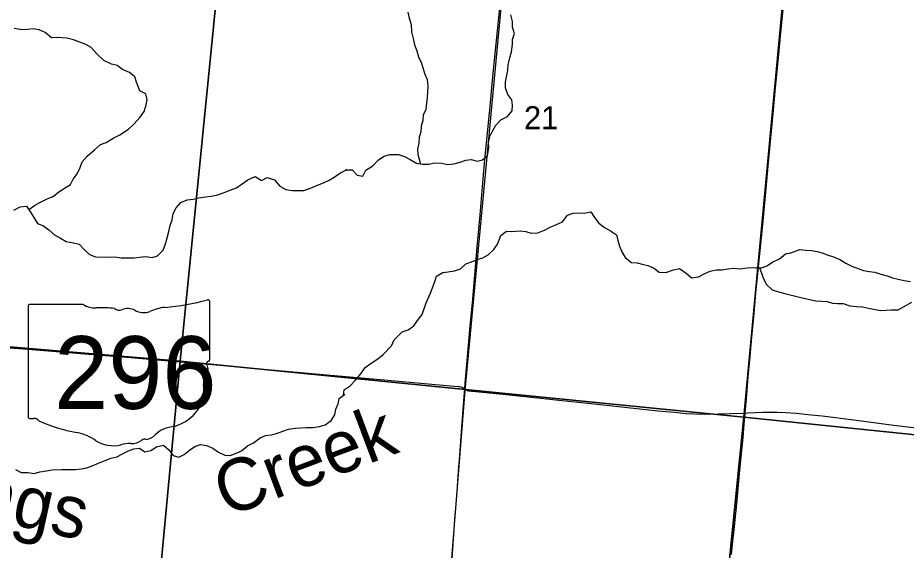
# Model space of a CAD drawing. Extents: x 0 to 1101, y 0 to 440.
# Drawn here: x 840.461 to 842.072, y 370.546 to 371.512 of the extents above; entities that cross this region are included whole.
import ezdxf

# ---------------------------------------------------------------- set-up
doc = ezdxf.new("R2010")
doc.units = 0
for name, color, linetype in [('GM_X_Minor_River', 7, 'Continuous'), ('GM_X_Minor_River_Text', 7, 'Continuous'), ('GM_X_Rail_Line', 7, 'Continuous'), ('GM_X_Section', 7, 'Continuous'), ('GM_X_Section_Text', 7, 'Continuous'), ('GM_X_State_Location', 7, 'Continuous'), ('GM_X_State_Route', 7, 'Continuous'), ('GM_X_State_Shield', 7, 'Continuous'), ('GM_X_Township_Road', 7, 'Continuous'), ('GM_X_US_Route', 7, 'Continuous')]:
    doc.layers.add(name, color=color, linetype=linetype)

msp = doc.modelspace()

# ---------------------------------------------------------------- linework, layer by layer
at = {"layer": 'GM_X_Minor_River'}
for points in [[(841.1684, 371.5223), (841.171, 371.5116), (841.1743, 371.5001), (841.1749, 371.4864), (841.1779, 371.4746), (841.1804, 371.4631), (841.1849, 371.452), (841.1875, 371.4413), (841.1931, 371.4295), (841.196, 371.4196), (841.1994, 371.4096), (841.2031, 371.4001), (841.2045, 371.3879), (841.2037, 371.378), (841.2032, 371.3673), (841.2023, 371.3574), (841.2011, 371.346), (841.196, 371.3354), (841.1952, 371.3255), (841.1924, 371.3152), (841.1916, 371.3053), (841.1888, 371.2954), (841.188, 371.2848), (841.186, 371.2737), (841.1863, 371.2638), (841.19, 371.2516), (841.1909, 371.2472)], [(841.0568, 371.2363), (841.0676, 371.2364), (841.0767, 371.2264), (841.0865, 371.2247), (841.092, 371.2354), (841.1046, 371.2436), (841.115, 371.2546), (841.1253, 371.261), (841.1356, 371.2639), (841.1516, 371.2642), (841.1623, 371.2606), (841.1725, 371.2552), (841.1838, 371.2482), (841.1949, 371.2466), (841.2063, 371.2465), (841.2166, 371.2487), (841.2295, 371.2486), (841.2406, 371.2462), (841.252, 371.2472), (841.2631, 371.2502), (841.2734, 371.2539), (841.2833, 371.2553), (841.2939, 371.2522), (841.3035, 371.2547), (841.313, 371.2615), (841.3154, 371.276), (841.3144, 371.2855), (841.3168, 371.2965), (841.3226, 371.3075), (841.3276, 371.317), (841.3372, 371.3272), (841.3491, 371.3332), (841.3575, 371.343), (841.358, 371.3533), (841.3566, 371.3632), (841.3494, 371.3728), (841.3457, 371.385), (841.3455, 371.3957), (841.3474, 371.4052), (841.3494, 371.4166), (841.3503, 371.4276), (841.3531, 371.4394), (841.3562, 371.4504), (841.3582, 371.4634), (841.3579, 371.4729), (841.3618, 371.4835), (841.3581, 371.495), (841.3582, 371.5056), (841.3553, 371.5175)], [(840.4808, 371.1642), (840.491, 371.1714), (840.501, 371.1768), (840.5141, 371.1836), (840.5252, 371.1882), (840.5353, 371.1963), (840.5469, 371.2039), (840.5566, 371.2094), (840.5611, 371.2195), (840.5689, 371.2292), (840.5738, 371.2408), (840.5779, 371.251), (840.5869, 371.261), (840.5998, 371.2724), (840.6111, 371.282), (840.6211, 371.2859), (840.6338, 371.2935), (840.6461, 371.2996), (840.6616, 371.3098), (840.6714, 371.3194), (840.6828, 371.332), (840.6903, 371.342), (840.694, 371.3541), (840.6955, 371.3639), (840.6931, 371.3739), (840.6822, 371.3796), (840.6762, 371.395), (840.6735, 371.4049), (840.6635, 371.4128), (840.6511, 371.4185), (840.6411, 371.4253), (840.6309, 371.4279), (840.6171, 371.4348), (840.6045, 371.4466), (840.5942, 371.4579), (840.5842, 371.4639), (840.5718, 371.4685), (840.562, 371.4718), (840.5499, 371.4752), (840.5318, 371.4765), (840.5219, 371.4757), (840.5104, 371.4851), (840.4999, 371.4904), (840.489, 371.4922), (840.4787, 371.491), (840.4692, 371.4905), (840.4541, 371.4929)], [(840.4539, 371.1629), (840.4655, 371.1691), (840.4765, 371.1706), (840.4838, 371.1598), (840.49, 371.1501), (840.4965, 371.1392), (840.5074, 371.1347), (840.5174, 371.1276), (840.5278, 371.1185), (840.5382, 371.1121), (840.549, 371.1061), (840.5622, 371.1041), (840.572, 371.1012), (840.5816, 371.0918), (840.5912, 371.0827), (840.6017, 371.0786), (840.6275, 371.0778), (840.637, 371.0787), (840.6487, 371.0764), (840.6605, 371.0765), (840.6715, 371.0765), (840.6814, 371.0781), (840.6928, 371.0789), (840.7045, 371.0774), (840.7145, 371.0802), (840.7243, 371.0906), (840.7288, 371.1022), (840.7321, 371.1128), (840.7348, 371.1245), (840.737, 371.1351), (840.7407, 371.1457), (840.7429, 371.157), (840.7481, 371.1671), (840.7568, 371.1771), (840.7679, 371.1818), (840.779, 371.183), (840.7893, 371.1853), (840.8011, 371.1872), (840.8114, 371.1885), (840.8236, 371.1911), (840.8351, 371.195), (840.8458, 371.1992), (840.8574, 371.2038), (840.8678, 371.2108), (840.8783, 371.2181), (840.8914, 371.2241), (840.9029, 371.217), (840.9133, 371.2224), (840.9265, 371.2182), (840.936, 371.2068), (840.9472, 371.2008), (840.9585, 371.1985), (840.968, 371.199), (840.9798, 371.1991), (840.9917, 371.2029), (841.0013, 371.2075), (841.0155, 371.2128), (841.0259, 371.2175), (841.0367, 371.224), (841.0464, 371.2309), (841.0568, 371.2363), (841.0561, 371.2371)], [(841.0517, 370.8274), (841.0526, 370.8371), (841.0637, 370.8442), (841.0726, 370.8541), (841.083, 370.8665), (841.0911, 370.8775), (841.1037, 370.8869), (841.1137, 370.8933), (841.1233, 370.9016), (841.1386, 370.9171), (841.1433, 370.9277), (841.1583, 370.9425), (841.169, 370.9462), (841.1793, 370.9533), (841.1859, 370.9628), (841.1943, 370.9738), (841.2014, 370.995), (841.2092, 371.0125), (841.2134, 371.0243), (841.2173, 371.0338), (841.2201, 371.0436), (841.232, 371.05), (841.2415, 371.0511), (841.2529, 371.0529), (841.2636, 371.0566), (841.2736, 371.066), (841.2839, 371.0697), (841.2942, 371.0738), (841.3045, 371.0768), (841.3141, 371.082), (841.3245, 371.0918), (841.3306, 371.1017), (841.3369, 371.1169), (841.3472, 371.1252), (841.3571, 371.1243), (841.372, 371.1257), (841.3822, 371.1244), (841.3921, 371.1217), (841.4039, 371.1223), (841.4162, 371.1268), (841.4265, 371.1324), (841.4379, 371.1369), (841.4486, 371.1421), (841.4579, 371.1538), (841.4682, 371.1576), (841.4785, 371.1582), (841.488, 371.1574), (841.5002, 371.1599), (841.507, 371.15), (841.5145, 371.1396), (841.5247, 371.1319), (841.5361, 371.1257), (841.5467, 371.1183), (841.5489, 371.108), (841.5522, 371.0981), (841.5563, 371.0874), (841.5627, 371.0774), (841.574, 371.0685), (841.5839, 371.0673), (841.5934, 371.0649), (841.6033, 371.0629), (841.6135, 371.0583), (841.6241, 371.0505), (841.6363, 371.05), (841.65, 371.0549), (841.6611, 371.0571), (841.6728, 371.0489), (841.683, 371.0401), (841.6952, 371.0422), (841.7067, 371.0482), (841.7163, 371.0527), (841.7281, 371.0549), (841.738, 371.0552), (841.7494, 371.0566), (841.7593, 371.0577), (841.77, 371.0568), (841.7795, 371.0578), (841.7894, 371.0593), (841.7989, 371.0584), (841.8104, 371.0587), (841.8203, 371.0628), (841.8299, 371.0696), (841.8421, 371.0748), (841.8529, 371.0838), (841.8628, 371.086), (841.8792, 371.092), (841.8898, 371.0903), (841.9005, 371.0899), (841.9104, 371.0882), (841.9199, 371.0855), (841.9305, 371.0816), (841.94, 371.0784), (841.9518, 371.0738), (841.9627, 371.0668), (841.9737, 371.0617), (841.9847, 371.0574), (841.9946, 371.0539), (842.0049, 371.0519), (842.0151, 371.0507), (842.0261, 371.0468), (842.0375, 371.044)], [(841.806, 371.0586), (841.8099, 371.0488), (841.8132, 371.0385), (841.8188, 371.0281), (841.829, 371.0189), (841.8404, 371.015), (841.8518, 371.0118), (841.8663, 371.0082), (841.8784, 371.0055), (841.8891, 371.0031), (841.9084, 370.9987), (841.9191, 370.9982), (841.9286, 370.9974), (841.9381, 370.9946), (841.9476, 370.9941), (841.9575, 370.9937), (841.9697, 370.9897), (841.9818, 370.9881), (841.9929, 370.9876), (842.0035, 370.9852), (842.016, 370.9828), (842.0263, 370.9812), (842.0454, 370.9822), (842.0572, 370.9824), (842.0671, 370.9877), (842.082, 370.9963)], [(842.0375, 371.044), (842.0474, 371.0405), (842.0573, 371.0381), (842.0683, 371.0353), (842.0801, 371.0337)], [(840.467, 370.6874), (840.4791, 370.687), (840.4904, 370.6852), (840.5008, 370.6887), (840.5133, 370.6902), (840.5233, 370.6922), (840.54, 370.6925), (840.5525, 370.6925), (840.5654, 370.6925), (840.5761, 370.6941), (840.586, 370.696), (840.5956, 370.6996), (840.6075, 370.7042), (840.6194, 370.7091), (840.6294, 370.713), (840.6405, 370.7157), (840.6509, 370.7211), (840.6617, 370.7265), (840.6712, 370.7301), (840.6819, 370.7316), (840.6916, 370.7245), (840.7023, 370.7272), (840.7127, 370.7338), (840.7253, 370.7368), (840.7349, 370.7282), (840.743, 370.7184), (840.7532, 370.7151), (840.7628, 370.7197), (840.7729, 370.7286), (840.783, 370.7351), (840.7925, 370.7383), (840.8031, 370.7364), (840.8144, 370.7315), (840.8248, 370.7243), (840.8364, 370.7187), (840.8462, 370.7184), (840.857, 370.7222), (840.8666, 370.7265), (840.8775, 370.7357), (840.8883, 370.7411), (840.9007, 370.7499), (840.9103, 370.7545), (840.9202, 370.7558), (840.9301, 370.7581), (840.9416, 370.762), (840.952, 370.7659), (840.9638, 370.7678), (840.9741, 370.7683), (840.9839, 370.7687), (840.9961, 370.7687), (841.0083, 370.7707), (841.0186, 370.7738), (841.0295, 370.7818), (841.0362, 370.7919), (841.038, 370.8021), (841.0417, 370.8119), (841.0435, 370.8218), (841.0536, 370.8287), (841.054, 370.8298)], [(840.4569, 370.693), (840.467, 370.6874)]]:
    msp.add_lwpolyline(points, dxfattribs=at)
at = {"layer": 'GM_X_Rail_Line'}
msp.add_lwpolyline([(841.0634, 368.7492), (841.0752, 368.8127), (841.0841, 368.8787), (841.1281, 369.2523), (841.1581, 369.5196), (841.193, 369.8378), (841.2158, 370.1274), (841.272, 370.836), (841.3678, 371.852), (841.4644, 372.7575), (841.4712, 372.8458), (841.5195, 373.3971), (841.577, 374.1201)], dxfattribs=at)
at = {"layer": 'GM_X_Section'}
for points in [[(839.8051, 371.9893), (840.8555, 371.8964), (840.7556, 370.8893), (839.7037, 370.9776)], [(841.873, 371.8071), (841.7775, 370.7877), (840.7556, 370.8893), (840.8555, 371.8964)], [(841.873, 371.8071), (842.9284, 371.7073), (842.8172, 370.6809), (841.7775, 370.7877)], [(839.7037, 370.9776), (840.7556, 370.8893), (840.6594, 369.8677), (839.6271, 369.9558)], [(840.7556, 370.8893), (841.7775, 370.7877), (841.6791, 369.8096), (840.6594, 369.8677)], [(842.8172, 370.6809), (842.711, 369.6847), (841.6791, 369.8096), (841.7775, 370.7877)]]:
    msp.add_lwpolyline(points, close=True, dxfattribs=at)
at = {"layer": 'GM_X_State_Route'}
for points in [[(840.4311, 370.9146), (840.4862, 370.9104), (840.5896, 370.9018), (840.6658, 370.8956), (840.7346, 370.8898), (840.8206, 370.8824), (840.9004, 370.8753), (840.9407, 370.8718), (841.0279, 370.8638), (841.1189, 370.8559), (841.2186, 370.8468), (841.2594, 370.8434), (841.2621, 370.8431), (841.2645, 370.8426), (841.2668, 370.8418), (841.2686, 370.8408), (841.2719, 370.8388)], [(841.2719, 370.8388), (841.2744, 370.8372), (841.2763, 370.8363), (841.2784, 370.8357), (841.281, 370.8352), (841.2838, 370.8349), (841.2916, 370.8341), (841.3467, 370.8286), (841.3745, 370.8255), (841.4147, 370.8214), (841.4419, 370.8186), (841.4956, 370.8128), (841.5611, 370.806), (841.6223, 370.7994), (841.6513, 370.7965), (841.673, 370.7945), (841.6886, 370.7938), (841.706, 370.7934), (841.7309, 370.7935), (841.7539, 370.7941), (841.7803, 370.7952)], [(841.7803, 370.7952), (841.7843, 370.7954), (841.8116, 370.7966), (841.8258, 370.7967), (841.8389, 370.7966), (841.8537, 370.7959), (841.8723, 370.7947), (841.8939, 370.7927), (841.9199, 370.7898), (841.9772, 370.7827), (842.045, 370.774), (842.1097, 370.7659), (842.1491, 370.7606), (842.2057, 370.7529), (842.2494, 370.7469), (842.2778, 370.7433), (842.2958, 370.7411)]]:
    msp.add_lwpolyline(points, dxfattribs=at)
at = {"layer": 'GM_X_State_Shield'}
for p, q in [((840.4797, 370.9887), (840.4797, 370.7885)), ((840.5794, 370.9921), (840.4829, 370.9921)), ((840.8093, 370.8924), (840.8093, 370.9971)), ((840.8092, 370.8924), (840.8093, 370.8924))]:
    msp.add_line(p, q, dxfattribs=at)
for centre, major_axis, start_param, end_param in [((840.4834, 370.9891), (0.00382, 0), 1.712693, 3.28349), ((840.6024, 371.0153), (0.037, 0), 4.042523, 4.731795), ((840.6918, 371.2649), (0.3495, 0), 4.814394, 5.042369), ((840.8056, 370.9975), (0.00367, 0), 6.141152, 7.989035), ((840.6147, 370.8798), (0.133, 0), 1.404758, 1.657858), ((840.6449, 370.9901), (0.0107, 0), 3.836095, 5.185415), ((840.6606, 370.967), (0.0222, 0), 0.950623, 2.079405), ((840.6892, 370.9987), (0.0267, 0), 4.081561, 5.145723), ((840.7364, 370.931), (0.0703, 0), 1.699011, 2.107814), ((840.8053, 370.892), (0.00393, 0), 5.05454, 6.418171), ((840.8084, 370.8847), (0.00568, 0), 1.883978, 3.671073), ((840.7723, 370.8715), (0.0341, 0), 5.934695, 6.695948), ((840.8224, 370.8486), (0.0248, 0), 2.387724, 3.262537), ((840.7114, 370.8352), (0.0874, 0), 5.101752, 6.440018), ((840.4835, 370.7881), (0.00385, 0), 3.00124, 4.508301), ((840.4841, 370.8086), (0.0294, 0), 4.665946, 4.897461), ((840.4901, 370.777), (0.0106, 0), 0.519207, 1.627899), ((840.6239, 370.9568), (0.2524, 0), 4.195997, 4.488961), ((840.7483, 370.7324), (0.0479, 0), 1.647645, 2.488434), ((840.5487, 370.6986), (0.079, 0), 0.823519, 1.323587), ((840.6667, 370.761), (0.0267, 0), 4.691044, 5.507374), ((840.6908, 370.7416), (0.00752, 0), 1.147584, 2.315152), ((840.6876, 370.7691), (0.0282, 0), 4.937069, 5.64225), ((840.6341, 370.776), (0.0501, 0), 4.026481, 4.996735), ((840.663, 370.7068), (0.0412, 0), 1.495662, 1.94098)]:
    msp.add_ellipse(centre, major_axis=major_axis, ratio=0.8, start_param=start_param, end_param=end_param, dxfattribs=at)
at = {"layer": 'GM_X_Township_Road'}
for points in [[(841.7803, 370.7952), (841.7808, 370.8013), (841.7822, 370.8212), (841.7857, 370.8608), (841.789, 370.8979), (841.7922, 370.9325), (841.7955, 370.9691), (841.7995, 371.013), (841.8041, 371.06), (841.8066, 371.0841), (841.8124, 371.1434), (841.818, 371.2022), (841.8218, 371.243), (841.8265, 371.2944), (841.8313, 371.3445), (841.8346, 371.3791), (841.8396, 371.4335), (841.8439, 371.4787), (841.8529, 371.5708)], [(841.7553, 370.5387), (841.7573, 370.5571), (841.7607, 370.5891), (841.7653, 370.6368), (841.7674, 370.6584), (841.7712, 370.698), (841.7761, 370.7506), (841.7783, 370.7752), (841.7803, 370.7952)]]:
    msp.add_lwpolyline(points, dxfattribs=at)
at = {"layer": 'GM_X_US_Route'}
for points in [[(841.2719, 370.8388), (841.2725, 370.8495), (841.2758, 370.8901), (841.2815, 370.9532), (841.2859, 371.0015), (841.2943, 371.0968), (841.2993, 371.1544), (841.305, 371.22), (841.3082, 371.2553), (841.3169, 371.345), (841.3233, 371.4118), (841.3308, 371.4884), (841.3381, 371.5614)], [(841.2484, 370.5309), (841.2535, 370.6019), (841.2571, 370.6446), (841.2609, 370.6973), (841.2617, 370.7103), (841.2664, 370.7698), (841.2712, 370.8323), (841.2719, 370.8388)]]:
    msp.add_lwpolyline(points, dxfattribs=at)

# ---------------------------------------------------------------- texts
at = {"layer": 'GM_X_Minor_River_Text'}
for s, height, rotation, p in [('Creek', 0.09469, 20.6145, (840.8393, 370.6056)), ('Kings', 0.0947, 347.6289, (840.2681, 370.6321))]:
    msp.add_text(s, height=height, rotation=rotation, dxfattribs=at).set_placement(p)
at = {"layer": 'GM_X_Section_Text'}
msp.add_text('21', height=0.04186, rotation=0, dxfattribs=at).set_placement((841.3789, 371.3099))
at = {"layer": 'GM_X_State_Location'}
for s, p in [('s', (840.6408, 370.8753)), ('r', (840.6407, 370.8753))]:
    msp.add_text(s, height=0.000189, dxfattribs=at).set_placement(p)
msp.add_text('296', height=0.000189, rotation=0, dxfattribs=at).set_placement((840.5739, 370.8615))
at = {"layer": 'GM_X_State_Shield'}
msp.add_text('296', height=0.13184, dxfattribs=at).set_placement((840.5271, 370.8027))

doc.saveas('drawing.dxf')
